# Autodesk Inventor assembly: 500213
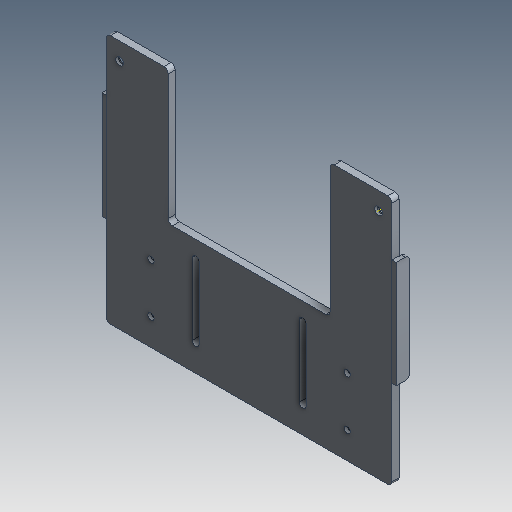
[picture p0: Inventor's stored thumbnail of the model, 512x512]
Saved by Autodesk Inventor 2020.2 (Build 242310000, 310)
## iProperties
Created: 1999-11
Part Number: 500213
Description: WMT-CP,FH,XX,PLATE,MNT,ERECTING_FINGER
Document SubType Name: Assembly
Designer: sspink
Mass: 2732.51 g
Surface Area: 2360.39 cm^2
Volume: 1008.31 cm^3
Density: 2.71 g/cm^3
Control State: 0
Checked Out: False
Last Check In By: gpurviance
Last Check In Date: 1999-12-16
Master: False
Shininess: 0.0
Length Units: 11269
Angle Units: 11279
Time Units: 11290
Mass Units: 11283
Length Display Precision: 3
Angle Display Precision: 2
Compacted: True
Dimensions: 355x19x418 mm
Mass: 2,733 kg
DocNumber: 500213.iam
Folder: 01 - Themengebiete\Simplification\01 - Packaging machine\
VDS_Category: 3D Komponenten
Density: 0.0
Volumn: 0.0
Area: 0.0
PropertySet Name: Model Information
Author: sspink
Revision Number: -
Title: WMT-CP,FH,XX,PLATE,MNT,ERECTING_FINGER
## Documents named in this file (3)
- D:\07 - DEMODATEN\OTX 2019 - Dataset - UPDATE - Dez2019\Designs\07-Packing machine\500213.iam
- D:\07 - DEMODATEN\OTX 2019 - Dataset - UPDATE - Dez2019\Designs\07-Packing machine\Parts\ADSK-011306.ipt
- D:\07 - DEMODATEN\OTX 2019 - Dataset - UPDATE - Dez2019\Designs\07-Packing machine\Parts\ADSK-011307.ipt
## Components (3 placed, 2 different names)
1. ADSK-011306:1 — Mate:1, Flush:1, Flush:2, Flush:3, Mate:2, Flush:4
2. ADSK-011307:1 — Mate:1, Flush:1, Flush:3
3. ADSK-011307:2 — Flush:2, Mate:2, Flush:4
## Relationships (6: Flush 4, Mate 2)
- Mate:1: ADSK-011306:1 ↔ ADSK-011307:1
- Flush:1: ADSK-011306:1 ↔ ADSK-011307:1
- Flush:2: ADSK-011306:1 ↔ ADSK-011307:2
- Flush:3: ADSK-011306:1 ↔ ADSK-011307:1
- Mate:2: ADSK-011306:1 ↔ ADSK-011307:2
- Flush:4: ADSK-011306:1 ↔ ADSK-011307:2
